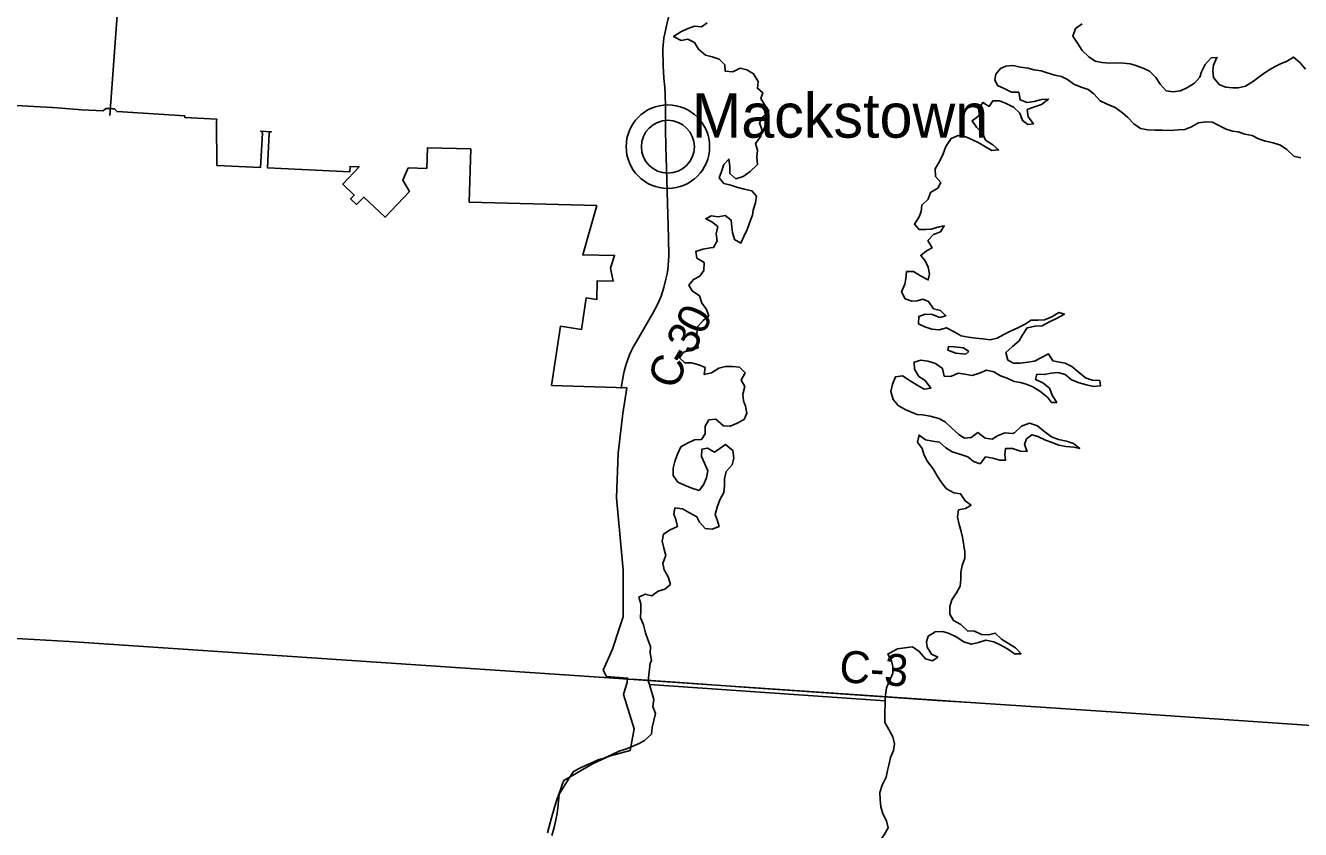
# Model space of a CAD drawing. Extents: x 1674899 to 2057726, y 653888 to 988278.
# Drawn here: x 1855438 to 1867438, y 775075 to 782644 of the extents above; entities that cross this region are included whole.
import ezdxf

# ---------------------------------------------------------------- set-up
doc = ezdxf.new("R2010")
doc.units = 0
for name, color, linetype in [('GM_X_Adjacent_County', 7, 'Continuous'), ('GM_X_Corporation', 7, 'Continuous'), ('GM_X_County', 7, 'Continuous'), ('GM_X_County_Road', 7, 'Continuous'), ('GM_X_County_Road_Text', 7, 'Continuous'), ('GM_X_Major_Lake', 7, 'Continuous'), ('GM_X_Township', 7, 'Continuous'), ('GM_X_Unincorporated', 7, 'Continuous'), ('GM_X_Unincorporated_Location', 7, 'Continuous'), ('GM_X_Unincorporated_Text', 7, 'Continuous')]:
    doc.layers.add(name, color=color, linetype=linetype)

msp = doc.modelspace()

# ---------------------------------------------------------------- linework, layer by layer
at = {"layer": 'GM_X_Adjacent_County'}
msp.add_lwpolyline([(1854746, 776908), (1855849, 776844), (1860837, 776510), (1864331, 776270), (1865938, 776163), (1868321, 776001), (1872401, 775756), (1872453, 775754), (1878568, 775400), (1881788, 775208), (1885545, 774992), (1886187, 774949), (1887084, 774902), (1887135, 774898), (1889887, 774731), (1895282, 774451), (1895251, 773958), (1895161, 772565), (1894704, 764108)], dxfattribs=at)
at = {"layer": 'GM_X_Corporation'}
msp.add_lwpolyline([(1855349, 781890), (1855515, 781881), (1855693, 781873), (1855739, 781870), (1855967, 781851), (1856168, 781841), (1856195, 781864), (1856211, 781863), (1856236, 781862), (1856261, 781860), (1856276, 781859), (1856299, 781833), (1856937, 781794), (1856936, 781779), (1857238, 781762), (1857236, 781737), (1857239, 781327), (1857650, 781308), (1857667, 781631), (1857667, 781633), (1857666, 781635), (1857665, 781638), (1857665, 781639), (1857663, 781642), (1857661, 781645), (1857661, 781645), (1857660, 781645), (1857658, 781647), (1857657, 781648), (1857656, 781648), (1857654, 781649), (1857652, 781650), (1857650, 781650), (1857750, 781644), (1857748, 781644), (1857746, 781643), (1857744, 781643), (1857743, 781642), (1857742, 781642), (1857739, 781640), (1857739, 781640), (1857739, 781639), (1857736, 781637), (1857734, 781634), (1857734, 781633), (1857732, 781631), (1857732, 781629), (1857731, 781626), (1857715, 781305), (1858491, 781268), (1858493, 781318), (1858578, 781314), (1858423, 781151), (1858532, 781048), (1858498, 781011), (1858552, 780960), (1858623, 781028), (1858823, 780839), (1859051, 781080), (1858990, 781189), (1859040, 781304), (1859215, 781299), (1859220, 781493), (1859628, 781482), (1859614, 780982), (1860814, 780950), (1860682, 780484), (1860982, 780480), (1860944, 780361), (1860968, 780237), (1860818, 780240), (1860815, 780064), (1860716, 780079), (1860671, 779783), (1860473, 779812), (1860389, 779255), (1861099, 779232), (1861059, 778991), (1861017, 778619), (1861001, 778196), (1861035, 777824), (1861063, 777515), (1861063, 777076), (1861027, 776964), (1860963, 776772), (1860875, 776576), (1860907, 776515), (1861104, 776501), (1861102, 776461), (1861067, 776346), (1861166, 776024), (1861129, 775818), (1860932, 775766), (1860782, 775695), (1860506, 775536), (1860490, 775500), (1860473, 775450), (1860446, 775373), (1860418, 775284), (1860408, 775252), (1860389, 775184), (1860366, 775102), (1860350, 775045)], dxfattribs=at)
at = {"layer": 'GM_X_County'}
msp.add_lwpolyline([(1881788, 775208), (1878568, 775400), (1872453, 775754), (1872401, 775756), (1868321, 776001), (1865938, 776163), (1864331, 776270), (1860837, 776510), (1855849, 776844), (1854746, 776908)], dxfattribs=at)
at = {"layer": 'GM_X_County_Road'}
for points in [[(1861455, 782568), (1861484, 782698), (1861529, 782870), (1861693, 783500), (1861750, 783702), (1861886, 784220), (1862013, 784736), (1862018, 784757), (1862066, 784939), (1862201, 785417), (1862338, 785941), (1862465, 786443), (1862569, 786870), (1862577, 786904), (1862585, 786934), (1862693, 787317), (1862818, 787780), (1862854, 787912), (1862860, 787938)], [(1856233, 781796), (1856351, 783427)], [(1861457, 781995), (1861454, 782060), (1861446, 782148), (1861441, 782263), (1861435, 782424), (1861446, 782529), (1861455, 782568)], [(1861464, 781502), (1861463, 781671), (1861461, 781880), (1861457, 781995)], [(1861042, 779227), (1861043, 779234), (1861066, 779359), (1861076, 779401), (1861095, 779466), (1861124, 779543), (1861142, 779583), (1861161, 779622), (1861188, 779670), (1861340, 779929), (1861381, 780006), (1861399, 780046), (1861420, 780097), (1861434, 780136), (1861446, 780176), (1861466, 780256), (1861476, 780305), (1861482, 780347), (1861487, 780389), (1861492, 780474), (1861490, 780645), (1861469, 781407), (1861464, 781502)], [(1861150, 776489), (1861724, 776449)], [(1861724, 776449), (1862245, 776413)], [(1862245, 776413), (1864018, 776291)], [(1864018, 776291), (1864331, 776270)], [(1864331, 776270), (1865938, 776163), (1868321, 776001)]]:
    msp.add_lwpolyline(points, dxfattribs=at)
at = {"layer": 'GM_X_Major_Lake'}
for points in [[(1861855, 782669), (1861799, 782631), (1861733, 782638), (1861667, 782614), (1861605, 782584), (1861538, 782541), (1861608, 782504), (1861672, 782514), (1861734, 782484), (1861771, 782421), (1861839, 782365), (1861901, 782348), (1861967, 782328), (1862020, 782274), (1862024, 782214), (1862096, 782209), (1862164, 782243), (1862226, 782227), (1862289, 782190), (1862335, 782118), (1862327, 782054), (1862378, 782010), (1862360, 781958), (1862394, 781899), (1862435, 781841), (1862381, 781787), (1862345, 781727), (1862368, 781665), (1862360, 781603), (1862309, 781533), (1862329, 781469), (1862321, 781403), (1862326, 781335), (1862258, 781269), (1862192, 781222), (1862124, 781202), (1862066, 781252), (1862068, 781319), (1862059, 781387), (1862010, 781335), (1861988, 781271), (1861968, 781211)], [(1865383, 782660), (1865321, 782615), (1865296, 782545), (1865338, 782478), (1865383, 782408), (1865445, 782349), (1865505, 782309), (1865569, 782296), (1865639, 782290), (1865703, 782292), (1865773, 782291), (1865835, 782283), (1865889, 782266), (1865964, 782238), (1866018, 782214), (1866078, 782153), (1866116, 782091), (1866175, 782030), (1866241, 782020), (1866309, 782029), (1866375, 782059), (1866440, 782101), (1866492, 782157), (1866508, 782209), (1866541, 782277), (1866599, 782340), (1866651, 782344), (1866619, 782272), (1866612, 782220), (1866618, 782154), (1866672, 782089), (1866733, 782063), (1866801, 782057), (1866851, 782058), (1866922, 782072), (1866996, 782120), (1867062, 782169)], [(1867062, 782169), (1867126, 782215), (1867195, 782255), (1867257, 782285), (1867307, 782304), (1867373, 782346), (1867431, 782296), (1867487, 782233)], [(1865618, 781905), (1865553, 781936), (1865493, 782000), (1865441, 782041), (1865373, 782065), (1865306, 782093), (1865244, 782136), (1865190, 782164), (1865126, 782177), (1865054, 782197), (1864998, 782216), (1864930, 782226), (1864876, 782242), (1864804, 782253), (1864732, 782267), (1864664, 782260), (1864614, 782238), (1864570, 782186), (1864560, 782134), (1864587, 782078), (1864655, 782049), (1864717, 782017), (1864787, 782016), (1864799, 781944), (1864866, 781918), (1864931, 781927), (1865001, 781947), (1865065, 781951), (1865000, 781901), (1864934, 781879), (1864866, 781853), (1864876, 781783), (1864925, 781717), (1864873, 781713), (1864821, 781749), (1864796, 781820), (1864736, 781876), (1864668, 781911), (1864605, 781935), (1864541, 781934), (1864508, 781882), (1864448, 781918), (1864412, 781864), (1864414, 781796), (1864347, 781748), (1864389, 781688), (1864449, 781625), (1864474, 781565), (1864542, 781521), (1864596, 781472), (1864534, 781468), (1864474, 781503), (1864410, 781541), (1864358, 781564), (1864287, 781596), (1864217, 781609), (1864150, 781581), (1864100, 781505), (1864076, 781435), (1864039, 781363), (1863999, 781295), (1864004, 781223), (1864052, 781165), (1864024, 781113), (1863955, 781073), (1863935, 781009), (1863873, 780953), (1863868, 780893), (1863850, 780843), (1863804, 780775), (1863849, 780723), (1863913, 780722), (1863963, 780728), (1864036, 780750), (1864086, 780757), (1864051, 780703), (1863985, 780678), (1863931, 780620), (1863970, 780550), (1863918, 780522), (1863864, 780480), (1863906, 780428), (1863935, 780369), (1863945, 780303), (1863935, 780249), (1863863, 780288), (1863795, 780328), (1863731, 780328), (1863723, 780260), (1863714, 780208), (1863684, 780136), (1863718, 780072), (1863781, 780048), (1863831, 780051), (1863884, 780067), (1863937, 780045), (1863983, 779978), (1864049, 779962), (1864101, 779911), (1864043, 779894), (1863973, 779924)], [(1867440, 781397), (1867376, 781414), (1867310, 781478), (1867250, 781519), (1867182, 781539), (1867109, 781556), (1867043, 781578), (1866985, 781607), (1866915, 781621), (1866851, 781643), (1866799, 781650), (1866739, 781668), (1866675, 781701), (1866610, 781733), (1866546, 781737), (1866478, 781728), (1866413, 781690), (1866351, 781666), (1866287, 781661), (1866211, 781657), (1866139, 781660), (1866067, 781658), (1866001, 781662), (1865931, 781675), (1865869, 781719), (1865814, 781778), (1865762, 781822), (1865694, 781871), (1865618, 781905)], [(1861968, 781211), (1862011, 781157), (1862077, 781140), (1862141, 781118), (1862203, 781104), (1862275, 781089), (1862318, 781037), (1862310, 780975), (1862286, 780907), (1862281, 780857), (1862259, 780803), (1862230, 780725), (1862198, 780657), (1862172, 780595), (1862110, 780630), (1862092, 780694), (1862085, 780746), (1862079, 780812), (1862024, 780856), (1861958, 780843), (1861892, 780853), (1861840, 780825), (1861899, 780795), (1861955, 780751), (1861939, 780683), (1861948, 780618), (1861914, 780555)], [(1861914, 780555), (1861884, 780551), (1861814, 780539), (1861746, 780517), (1861757, 780455), (1861825, 780413), (1861823, 780339), (1861784, 780285), (1861724, 780253), (1861682, 780199), (1861714, 780147), (1861781, 780099), (1861803, 780029), (1861844, 779976), (1861868, 779912), (1861816, 779866), (1861765, 779809), (1861755, 779745), (1861759, 779682), (1861768, 779610), (1861700, 779589), (1861632, 779569), (1861592, 779515), (1861645, 779467), (1861705, 779467), (1861775, 779450), (1861835, 779424), (1861827, 779358), (1861893, 779375), (1861963, 779417), (1862027, 779433), (1862091, 779434), (1862159, 779426), (1862212, 779374), (1862174, 779306), (1862207, 779244), (1862189, 779172), (1862197, 779110), (1862214, 779059), (1862228, 778995), (1862202, 778935), (1862131, 778898), (1862069, 778872), (1862009, 778874), (1861936, 778937), (1861870, 778931), (1861836, 778871), (1861835, 778801), (1861801, 778747), (1861735, 778742), (1861669, 778712), (1861607, 778676), (1861576, 778610), (1861550, 778540), (1861535, 778476), (1861535, 778408), (1861579, 778346), (1861640, 778316), (1861710, 778289), (1861778, 778267), (1861820, 778321), (1861847, 778385), (1861859, 778453), (1861829, 778523), (1861802, 778587), (1861804, 778655), (1861856, 778665), (1861924, 778628), (1861974, 778662), (1862026, 778700), (1862094, 778644), (1862105, 778571), (1862089, 778509), (1862033, 778444), (1862018, 778376), (1862018, 778312), (1862012, 778248), (1861973, 778180), (1861947, 778110), (1861930, 778042), (1861948, 777990), (1861966, 777928), (1861900, 777902), (1861834, 777908), (1861782, 777967), (1861758, 778019), (1861687, 778057), (1861621, 778094), (1861551, 778102), (1861539, 778044), (1861560, 777994), (1861574, 777928), (1861506, 777896), (1861444, 777856), (1861431, 777790), (1861447, 777724), (1861464, 777654), (1861436, 777582), (1861450, 777520), (1861487, 777454), (1861509, 777383)], [(1863973, 779924), (1863907, 779928), (1863845, 779903), (1863842, 779837), (1863902, 779808), (1863968, 779784), (1864036, 779779), (1864106, 779799), (1864180, 779759), (1864246, 779724), (1864314, 779710), (1864381, 779701), (1864447, 779693), (1864517, 779684), (1864582, 779700), (1864646, 779734), (1864708, 779765), (1864778, 779797), (1864842, 779829), (1864903, 779869), (1864967, 779870), (1865029, 779874), (1865099, 779902), (1865165, 779943), (1865217, 779927), (1865147, 779889), (1865076, 779854), (1865008, 779818), (1864940, 779814), (1864866, 779799), (1864820, 779727), (1864789, 779675), (1864729, 779621), (1864665, 779565), (1864684, 779495), (1864736, 779465), (1864800, 779466), (1864872, 779476), (1864934, 779485), (1865000, 779519), (1865065, 779553), (1865106, 779488), (1865170, 779476), (1865222, 779466), (1865286, 779435), (1865346, 779383), (1865415, 779326), (1865479, 779306), (1865549, 779301), (1865555, 779251), (1865491, 779246), (1865423, 779262), (1865355, 779281), (1865283, 779307), (1865222, 779358), (1865154, 779378), (1865092, 779370), (1865026, 779357), (1864958, 779361), (1864945, 779311), (1865013, 779281), (1865077, 779230), (1865104, 779158), (1865144, 779095), (1865094, 779096), (1865056, 779146), (1864985, 779201), (1864919, 779243), (1864857, 779269), (1864803, 779282), (1864743, 779294), (1864677, 779323), (1864615, 779345), (1864552, 779383), (1864482, 779400), (1864418, 779370), (1864349, 779349), (1864278, 779363), (1864216, 779371), (1864147, 779340), (1864083, 779344), (1864068, 779416), (1864004, 779461), (1863932, 779485), (1863866, 779492), (1863802, 779476), (1863804, 779408), (1863845, 779341), (1863907, 779301), (1863959, 779231), (1863897, 779219), (1863831, 779257), (1863763, 779300), (1863693, 779346), (1863625, 779335), (1863597, 779267), (1863584, 779197), (1863604, 779124), (1863650, 779068), (1863716, 779030), (1863767, 779007)], [(1864317, 779575), (1864265, 779608), (1864179, 779618), (1864125, 779621), (1864119, 779588)], [(1864119, 779588), (1864195, 779558), (1864289, 779551), (1864317, 779575)], [(1863767, 779007), (1863829, 778981), (1863881, 778978), (1863953, 778966), (1864033, 778943), (1864093, 778913), (1864157, 778853), (1864224, 778794), (1864276, 778760), (1864340, 778765), (1864402, 778811), (1864470, 778758), (1864536, 778750), (1864586, 778780), (1864656, 778810), (1864724, 778803)], [(1864724, 778803), (1864748, 778809), (1864813, 778871), (1864889, 778900), (1864963, 778876), (1865020, 778827), (1865094, 778773), (1865160, 778746), (1865236, 778732), (1865302, 778708), (1865360, 778661), (1865304, 778673), (1865230, 778680), (1865164, 778692), (1865092, 778721), (1865038, 778741), (1864966, 778776), (1864910, 778792), (1864858, 778752), (1864842, 778700), (1864865, 778634), (1864803, 778638), (1864729, 778663), (1864663, 778663), (1864655, 778601), (1864663, 778551), (1864607, 778551), (1864543, 778572), (1864475, 778582), (1864423, 778518), (1864361, 778539), (1864307, 778583), (1864233, 778608), (1864161, 778630), (1864101, 778668), (1864042, 778723), (1863976, 778731), (1863908, 778744), (1863848, 778788), (1863834, 778722), (1863877, 778662), (1863897, 778599), (1863929, 778539), (1863980, 778469), (1864018, 778404), (1864058, 778342), (1864107, 778281), (1864175, 778243), (1864239, 778235), (1864281, 778168), (1864338, 778128), (1864284, 778096), (1864220, 778084), (1864210, 778014), (1864225, 777946), (1864243, 777882), (1864257, 777826), (1864280, 777689), (1864279, 777629), (1864255, 777561), (1864241, 777495), (1864240, 777429), (1864236, 777365), (1864200, 777303), (1864157, 777237), (1864137, 777173), (1864138, 777103), (1864172, 777044), (1864242, 777006), (1864303, 776945), (1864369, 776943), (1864437, 776912), (1864503, 776908), (1864565, 776924), (1864625, 776867), (1864691, 776825), (1864757, 776784), (1864808, 776730), (1864746, 776730), (1864680, 776777), (1864613, 776813), (1864551, 776842), (1864477, 776856), (1864409, 776836), (1864339, 776819), (1864269, 776843), (1864199, 776888), (1864133, 776920), (1864071, 776939), (1864001, 776937), (1863935, 776895), (1863917, 776841), (1863923, 776791), (1863964, 776727), (1864024, 776698), (1863974, 776664), (1863908, 776683), (1863850, 776751), (1863785, 776794), (1863714, 776784), (1863646, 776775)], [(1861509, 777383), (1861455, 777338), (1861393, 777320), (1861334, 777276), (1861270, 777289), (1861210, 777263), (1861228, 777199), (1861228, 777137), (1861225, 777069), (1861255, 777002), (1861274, 776926), (1861296, 776864), (1861319, 776798), (1861317, 776734), (1861329, 776670), (1861325, 776651)], [(1863530, 776285), (1863531, 776343), (1863543, 776410), (1863569, 776475), (1863601, 776547), (1863602, 776611), (1863590, 776662), (1863554, 776726), (1863646, 776775)], [(1861325, 776651), (1861316, 776642), (1861300, 776475), (1861311, 776439)], [(1861311, 776439), (1861353, 776299), (1861341, 776233), (1861369, 776167), (1861352, 776100), (1861336, 776036), (1861330, 775972), (1861265, 775914), (1861215, 775886), (1861148, 775857), (1861094, 775835), (1861026, 775811), (1860953, 775777), (1860885, 775748), (1860834, 775734), (1860780, 775708), (1860730, 775686), (1860661, 775656), (1860597, 775620), (1860548, 775548), (1860500, 775475), (1860461, 775408), (1860453, 775342), (1860448, 775280), (1860442, 775230), (1860430, 775166), (1860413, 775094), (1860393, 775020)], [(1863530, 776285), (1861311, 776439)], [(1861311, 776439), (1863530, 776285)], [(1863615, 774908), (1863548, 774882), (1863480, 774888), (1863468, 774956), (1863521, 775024), (1863557, 775090), (1863542, 775157), (1863508, 775221), (1863488, 775289), (1863481, 775357), (1863479, 775422), (1863501, 775492), (1863538, 775568), (1863552, 775630), (1863565, 775680), (1863579, 775752), (1863608, 775818), (1863616, 775880), (1863600, 775948), (1863564, 776015), (1863525, 776083), (1863527, 776149), (1863530, 776285)]]:
    msp.add_lwpolyline(points, dxfattribs=at)
at = {"layer": 'GM_X_Township'}
msp.add_lwpolyline([(1868734, 783178), (1868439, 777975), (1868321, 776001), (1865938, 776163), (1864331, 776270), (1860837, 776510), (1855849, 776844), (1854746, 776908)], dxfattribs=at)
at = {"layer": 'GM_X_Unincorporated'}
for radius in [393, 249]:
    msp.add_circle((1861484, 781503), radius, dxfattribs=at)
at = {"layer": 'GM_X_Unincorporated_Location'}
msp.add_line((1861484, 781503), (1861484, 781503), dxfattribs=at)

# ---------------------------------------------------------------- texts
at = {"layer": 'GM_X_County_Road_Text'}
for s, rotation, p in [('0', 65.1157, (1861818, 779719)), ('3', 59.6867, (1861710, 779532)), ('-', 59.403, (1861647, 779425)), ('C', 70.2486, (1861570, 779207)), ('C-3', 356.0607, (1863091, 776464))]:
    msp.add_text(s, height=300, rotation=rotation, dxfattribs=at).set_placement(p)
at = {"layer": 'GM_X_Unincorporated_Text'}
msp.add_text('Mackstown', height=417, rotation=0, dxfattribs=at).set_placement((1861710, 781588))

doc.saveas('drawing.dxf')
